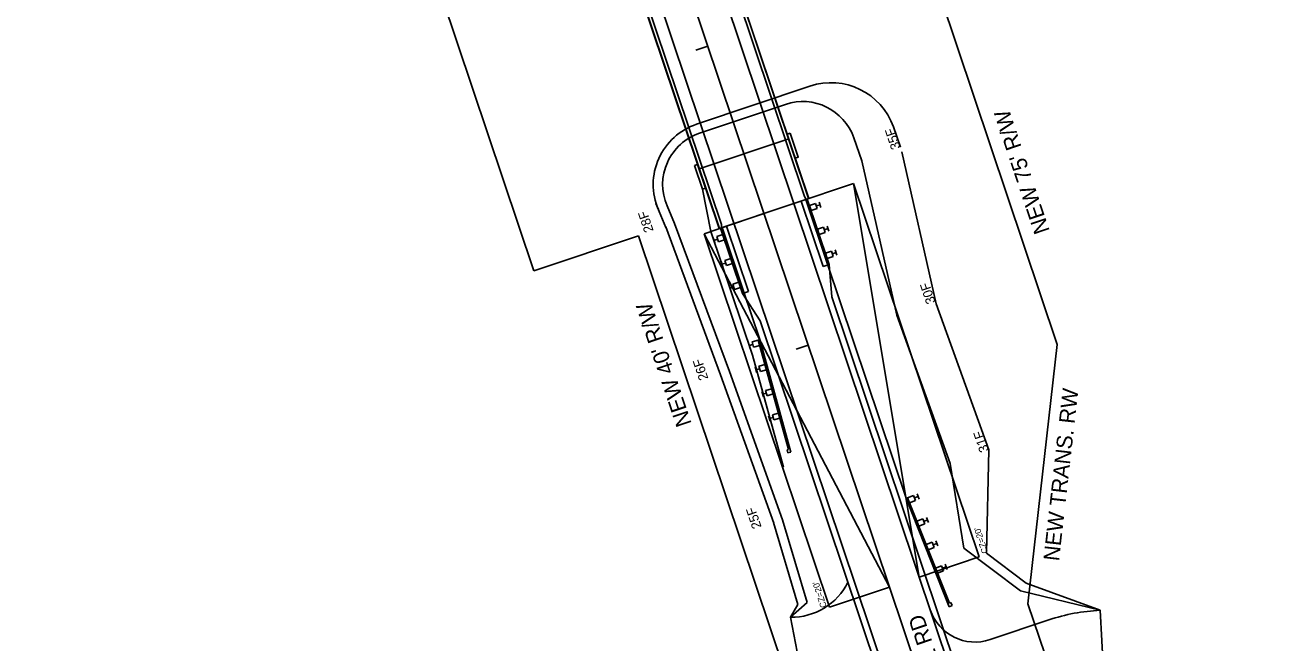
# Model space of a CAD drawing. Extents: x 1528853 to 1624411, y 1119753 to 1162242.
# Drawn here: x 1529554.1 to 1529951.4, y 1159723.3 to 1159919.3 of the extents above; entities that cross this region are included whole.
import ezdxf

# ---------------------------------------------------------------- set-up
doc = ezdxf.new("R2010")
doc.units = 0
for name, color, linetype in [('BR_CONCRETE', 7, 'Continuous'), ('BR_PROPOSED_CONTOUR', 7, 'Continuous'), ('RD_EX_Road Text', 7, 'Continuous'), ('RD_HC_Cl', 7, 'Continuous'), ('RD_HC_Data_Tic', 7, 'Continuous'), ('RD_PD_BOC', 7, 'Continuous'), ('RD_PD_CstnLmt', 7, 'Continuous'), ('RD_PD_CstnLmt_TX', 7, 'Continuous'), ('RD_PD_DR_ErosCtrl', 7, 'Continuous'), ('RD_PD_Driveway', 7, 'Continuous'), ('RD_PD_Final_TrvlWay', 7, 'Continuous'), ('RD_PD_GR', 7, 'Continuous'), ('RD_PD_PaveShd', 7, 'Continuous'), ('RD_PD_RW', 7, 'Continuous'), ('RD_Sketch8', 7, 'Continuous')]:
    doc.layers.add(name, color=color, linetype=linetype)

# ---------------------------------------------------------------- blocks, each defined once
blk = doc.blocks.new('Guardrail_MTBBC2_Transition')
at = {"layer": 'RD_PD_GR'}
for p, q in [((0, 0.5), (0, 0)), ((21.25, 0.5), (0, 0.5)), ((0, 0), (21.25, 0)), ((3.875, 3.75), (2.125, 3.75)), ((2.125, 0.5), (2.125, 2.5)), ((2.125, 2.5), (3.875, 2.5)), ((3.875, 0.5), (2.125, 0.5)), ((3, 2.5), (3, 3.75)), ((3.875, 2.5), (3.875, 0.5)), ((11.875, 3.75), (10.125, 3.75)), ((10.125, 0.5), (10.125, 2.5)), ((10.125, 2.5), (11.875, 2.5)), ((11.875, 0.5), (10.125, 0.5)), ((11, 2.5), (11, 3.75)), ((11.875, 2.5), (11.875, 0.5)), ((15, 0.5), (15, 0)), ((19.875, 3.75), (18.125, 3.75)), ((18.125, 0.5), (18.125, 2.5)), ((18.125, 2.5), (19.875, 2.5)), ((19.875, 0.5), (18.125, 0.5)), ((19, 2.5), (19, 3.75)), ((19.875, 2.5), (19.875, 0.5)), ((21.25, 0), (21.25, 0.5))]:
    blk.add_line(p, q, dxfattribs=at)

msp = doc.modelspace()

# ---------------------------------------------------------------- linework, layer by layer
at = {"layer": 'BR_CONCRETE'}
for p, q in [((1529801.49, 1159864.88), (1529767.1, 1159967.26)), ((1529802.75, 1159864.25), (1529767.73, 1159968.53)), ((1529802.83, 1159864.28), (1529767.81, 1159968.55)), ((1529774.39, 1159854.72), (1529739.37, 1159959)), ((1529774.47, 1159854.75), (1529739.45, 1159959.03)), ((1529775.1, 1159856.02), (1529740.71, 1159958.4)), ((1529768.03, 1159873.68), (1529796.46, 1159883.24)), ((1529774.39, 1159854.72), (1529802.83, 1159864.28)), ((1529801.49, 1159864.88), (1529802.04, 1159864.01)), ((1529775.1, 1159856.02), (1529775.18, 1159854.99))]:
    msp.add_line(p, q, dxfattribs=at)
for points in [[(1529796.93, 1159884.98), (1529795.99, 1159884.66), (1529798.53, 1159877.07), (1529799.48, 1159877.39)], [(1529766.6, 1159874.79), (1529767.55, 1159875.11), (1529770.1, 1159867.52), (1529769.15, 1159867.2)]]:
    msp.add_lwpolyline(points, close=True, dxfattribs=at)
at = {"layer": 'BR_PROPOSED_CONTOUR'}
msp.add_lwpolyline([(1529769.15, 1159867.2), (1529771.79, 1159853.85), (1529784.97, 1159814.61), (1529794.82, 1159779.04)], dxfattribs=at)
at = {"layer": 'RD_HC_Cl'}
msp.add_line((1529913.5, 1159487.74), (1529500.12, 1160718.34), dxfattribs=at)
at = {"layer": 'RD_HC_Data_Tic'}
for p, q in [((1529770.78, 1159912.59), (1529766.99, 1159911.31)), ((1529802.62, 1159817.79), (1529798.83, 1159816.52))]:
    msp.add_line(p, q, dxfattribs=at)
at = {"layer": 'RD_PD_BOC'}
for p, q in [((1529800.38, 1159863.49), (1529807.36, 1159842.71)), ((1529802.28, 1159864.12), (1529809.26, 1159843.35)), ((1529774.87, 1159854.88), (1529781.85, 1159834.11)), ((1529776.76, 1159855.52), (1529783.74, 1159834.75)), ((1529807.36, 1159842.71), (1529809.26, 1159843.35)), ((1529783.74, 1159834.75), (1529781.85, 1159834.11))]:
    msp.add_line(p, q, dxfattribs=at)
at = {"layer": 'RD_PD_CstnLmt'}
for p, q in [((1529795.41, 1159894.16), (1529768.18, 1159885.01)), ((1529819.67, 1159876.26), (1529817.1, 1159883.57)), ((1529830.79, 1159827.25), (1529819.67, 1159876.26)), ((1529760.26, 1159856.31), (1529757.85, 1159861.96)), ((1529777.64, 1159809.4), (1529760.26, 1159856.31)), ((1529847.71, 1159780.19), (1529830.79, 1159827.25)), ((1529794.52, 1159762.32), (1529777.64, 1159809.4)), ((1529852.09, 1159753.38), (1529847.71, 1159780.19)), ((1529802.31, 1159736.15), (1529794.52, 1159762.32)), ((1529870.01, 1159739.8), (1529852.09, 1159753.38)), ((1529895.32, 1159733.63), (1529870.01, 1159739.8)), ((1529797.04, 1159731.42), (1529802.31, 1159736.15))]:
    msp.add_line(p, q, dxfattribs=at)
for centre, start, end in [((1529800.89, 1159877.87), 19.3726, 108.568), ((1529773.65, 1159868.72), 108.568, 203.162)]:
    msp.add_arc(centre, 17.19, start, end, dxfattribs=at)
at = {"layer": 'RD_PD_DR_ErosCtrl'}
for p, q in [((1529803.18, 1159899.93), (1529767.22, 1159887.85)), ((1529831.93, 1159880.57), (1529829.68, 1159886.99)), ((1529843.29, 1159830.9), (1529832.35, 1159879.14)), ((1529757.51, 1159855.13), (1529754.25, 1159862.73)), ((1529774.82, 1159808.37), (1529757.45, 1159855.26)), ((1529859.94, 1159784.59), (1529843.29, 1159830.9)), ((1529791.7, 1159761.31), (1529774.82, 1159808.37)), ((1529859.23, 1159751.73), (1529859.94, 1159784.59)), ((1529799.37, 1159735.51), (1529791.64, 1159761.47)), ((1529871.82, 1159742.19), (1529859.23, 1159751.73)), ((1529895.32, 1159733.63), (1529871.82, 1159742.19)), ((1529797.04, 1159731.42), (1529799.37, 1159735.51))]:
    msp.add_line(p, q, dxfattribs=at)
for centre, radius, start, end in [((1529809.87, 1159880.03), 21, 19.3726, 108.568), ((1529773.65, 1159868.72), 20.19, 108.568, 203.162)]:
    msp.add_arc(centre, radius, start, end, dxfattribs=at)
at = {"layer": 'RD_PD_Driveway'}
for p, q in [((1529797.04, 1159731.42), (1529800.23, 1159714.99)), ((1529895.32, 1159733.63), (1529896.42, 1159712.77)), ((1529879.01, 1159730.57), (1529860.4, 1159724.32))]:
    msp.add_line(p, q, dxfattribs=at)
for centre, radius, start, end in [((1529797.32, 1159751.42), 20, 269.2153, 333.671), ((1529855.62, 1159738.54), 15, 198.568, 288.568), ((1529898.11, 1159673.7), 60, 92.6717, 108.568)]:
    msp.add_arc(centre, radius, start, end, dxfattribs=at)
at = {"layer": 'RD_PD_Final_TrvlWay'}
for p, q in [((1529922.97, 1159490.92), (1529689.19, 1160186.88)), ((1529904.02, 1159484.55), (1529670.23, 1160180.51))]:
    msp.add_line(p, q, dxfattribs=at)
at = {"layer": 'RD_PD_GR'}
for p, q in [((1529833.73, 1159769.16), (1529808.65, 1159843.82)), ((1529787.28, 1159819.5), (1529782.11, 1159834.9)), ((1529784.14, 1159816.81), (1529783.67, 1159818.49)), ((1529786.8, 1159819.36), (1529784.87, 1159818.83)), ((1529784.87, 1159818.83), (1529785.34, 1159817.14)), ((1529786.8, 1159819.36), (1529787.28, 1159819.5)), ((1529787.27, 1159817.68), (1529786.8, 1159819.36)), ((1529796.41, 1159784.67), (1529786.8, 1159819.36)), ((1529787.28, 1159819.5), (1529797.16, 1159783.84)), ((1529785.11, 1159817.98), (1529783.9, 1159817.65)), ((1529785.34, 1159817.14), (1529787.27, 1159817.68)), ((1529786.27, 1159809.1), (1529785.8, 1159810.78)), ((1529788.94, 1159811.65), (1529787.01, 1159811.12)), ((1529787.01, 1159811.12), (1529787.48, 1159809.43)), ((1529789.4, 1159809.97), (1529788.94, 1159811.65)), ((1529787.24, 1159810.27), (1529786.04, 1159809.94)), ((1529787.48, 1159809.43), (1529789.4, 1159809.97)), ((1529788.41, 1159801.39), (1529787.94, 1159803.07)), ((1529789.38, 1159802.56), (1529788.17, 1159802.23)), ((1529791.07, 1159803.94), (1529789.14, 1159803.41)), ((1529789.14, 1159803.41), (1529789.61, 1159801.72)), ((1529791.54, 1159802.26), (1529791.07, 1159803.94)), ((1529789.61, 1159801.72), (1529791.54, 1159802.26)), ((1529790.54, 1159793.68), (1529790.07, 1159795.36)), ((1529791.51, 1159794.85), (1529790.31, 1159794.52)), ((1529793.21, 1159796.23), (1529791.28, 1159795.7)), ((1529791.28, 1159795.7), (1529791.74, 1159794.01)), ((1529793.67, 1159794.55), (1529793.21, 1159796.23)), ((1529791.74, 1159794.01), (1529793.67, 1159794.55)), ((1529795.47, 1159788.04), (1529795.95, 1159788.17)), ((1529795.92, 1159784.53), (1529796.4, 1159784.67)), ((1529796.19, 1159783.57), (1529795.92, 1159784.53)), ((1529797.16, 1159783.84), (1529796.19, 1159783.57)), ((1529834.19, 1159769.35), (1529833.73, 1159769.16)), ((1529833.73, 1159769.16), (1529847.39, 1159734.78)), ((1529834.19, 1159769.35), (1529836.05, 1159770.09)), ((1529834.84, 1159767.72), (1529834.19, 1159769.35)), ((1529847.48, 1159735.89), (1529834.19, 1159769.35)), ((1529836.7, 1159768.46), (1529834.84, 1159767.72)), ((1529836.05, 1159770.09), (1529836.7, 1159768.46)), ((1529836.37, 1159769.27), (1529837.54, 1159769.74)), ((1529837.86, 1159768.92), (1529837.21, 1159770.55)), ((1529840.81, 1159761.49), (1529840.17, 1159763.11)), ((1529837.15, 1159761.91), (1529839, 1159762.65)), ((1529837.79, 1159760.29), (1529837.15, 1159761.91)), ((1529839.65, 1159761.03), (1529837.79, 1159760.29)), ((1529839, 1159762.65), (1529839.65, 1159761.03)), ((1529839.33, 1159761.84), (1529840.49, 1159762.3)), ((1529840.1, 1159754.48), (1529841.96, 1159755.22)), ((1529841.96, 1159755.22), (1529842.6, 1159753.59)), ((1529842.28, 1159754.4), (1529843.44, 1159754.87)), ((1529843.77, 1159754.05), (1529843.12, 1159755.68)), ((1529840.74, 1159752.85), (1529840.1, 1159754.48)), ((1529842.6, 1159753.59), (1529840.74, 1159752.85)), ((1529843.05, 1159747.04), (1529844.91, 1159747.78)), ((1529843.7, 1159745.42), (1529843.05, 1159747.04)), ((1529844.91, 1159747.78), (1529845.56, 1159746.16)), ((1529845.23, 1159746.97), (1529846.4, 1159747.43)), ((1529846.72, 1159746.62), (1529846.07, 1159748.24)), ((1529845.56, 1159746.16), (1529843.7, 1159745.42)), ((1529846.19, 1159739.14), (1529845.72, 1159738.96)), ((1529847.39, 1159734.78), (1529848.32, 1159735.15)), ((1529847.95, 1159736.08), (1529847.48, 1159735.89)), ((1529848.32, 1159735.15), (1529847.95, 1159736.08))]:
    msp.add_line(p, q, dxfattribs=at)
at = {"layer": 'RD_PD_PaveShd'}
for p, q in [((1529809.33, 1159843.37), (1529810.14, 1159833.1)), ((1529781.85, 1159834.11), (1529787.4, 1159825.43)), ((1529924.87, 1159491.56), (1529810.14, 1159833.1)), ((1529902.12, 1159483.92), (1529787.4, 1159825.43))]:
    msp.add_line(p, q, dxfattribs=at)
at = {"layer": 'RD_PD_RW'}
for p, q in [((1529881.68, 1159817.98), (1529571.21, 1160742.22)), ((1529715.61, 1159841.31), (1529429.02, 1160694.46)), ((1529748.79, 1159852.45), (1529715.61, 1159841.31)), ((1529796.55, 1159710.26), (1529748.79, 1159852.45)), ((1529872.39, 1159735.73), (1529881.68, 1159817.98)), ((1529951.41, 1159500.47), (1529872.39, 1159735.73))]:
    msp.add_line(p, q, dxfattribs=at)
at = {"layer": 'RD_Sketch8'}
for p, q in [((1529798.09, 1159862.69), (1529817.05, 1159869.05)), ((1529837.9, 1159744.19), (1529817.05, 1159869.05)), ((1529856.86, 1159750.56), (1529817.05, 1159869.05)), ((1529788.61, 1159859.5), (1529769.66, 1159853.13)), ((1529828.42, 1159741.01), (1529769.66, 1159853.13)), ((1529809.46, 1159734.64), (1529769.66, 1159853.13)), ((1529837.9, 1159744.19), (1529856.86, 1159750.56)), ((1529828.42, 1159741.01), (1529809.46, 1159734.64))]:
    msp.add_line(p, q, dxfattribs=at)

# ---------------------------------------------------------------- block references
at = {"layer": 'RD_PD_BOC', "rotation": -71.4319942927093}
msp.add_blockref('Guardrail_MTBBC2_Transition', (1529801.89, 1159863.96), dxfattribs=at)
at = {"layer": 'RD_PD_BOC', "yscale": -0.9999999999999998, "rotation": -71.43199429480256}
msp.add_blockref('Guardrail_MTBBC2_Transition', (1529775.34, 1159855.04), dxfattribs=at)

# ---------------------------------------------------------------- texts
at = {"layer": 'RD_EX_Road Text'}
msp.add_text('S-26 PACE BRIDGE RD', height=5, rotation=108.5527, dxfattribs=at).set_placement((1529862.31, 1159663.38))
at = {"layer": 'RD_PD_CstnLmt_TX'}
for s, p in [('35F', (1529831.99, 1159880.4)), ('28F', (1529753.63, 1159854.08)), ('30F', (1529843.11, 1159831.39)), ('26F', (1529771.01, 1159807.17)), ('31F', (1529860.03, 1159784.33)), ('25F', (1529787.88, 1159760.09))]:
    msp.add_text(s, height=3, rotation=108.568, dxfattribs=at).set_placement(p)
at = {"layer": 'RD_PD_RW'}
for s, rotation, p in [("NEW 75' R/W", 108.5527, (1529879.35, 1159854.03)), ("NEW 40' R/W", 108.5527, (1529765.72, 1159792.86)), ('NEW TRANS. RW', 83.5511, (1529882.24, 1159749.09))]:
    msp.add_text(s, height=5, rotation=rotation, dxfattribs=at).set_placement(p)
at = {"layer": 'RD_Sketch8'}
for p in [(1529859.8, 1159752.02), (1529808.57, 1159734.81)]:
    msp.add_text("CZ=20'", height=2, rotation=108.3453, dxfattribs=at).set_placement(p)

doc.saveas('drawing.dxf')
